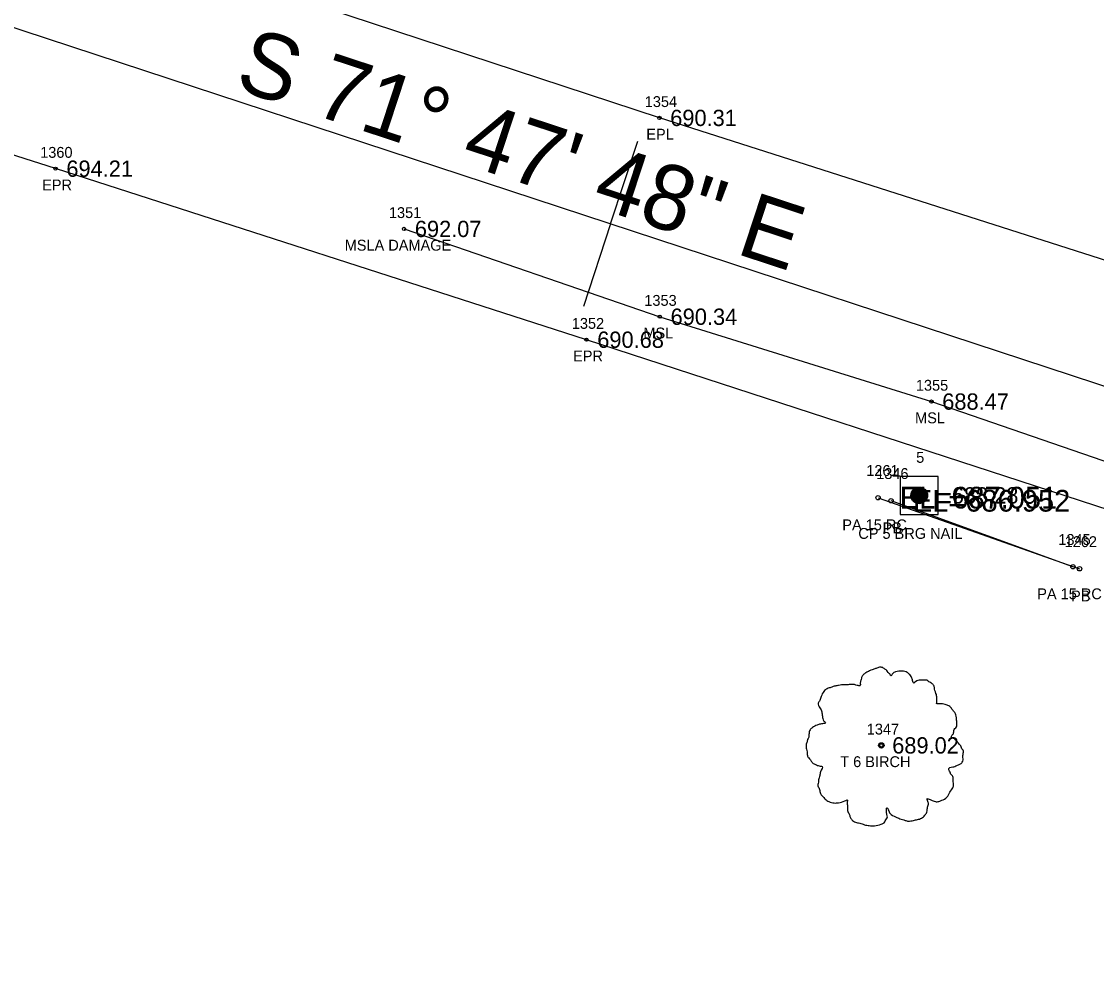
# Model space of a CAD drawing. Extents: x 1655137 to 1657928, y 1003994 to 1005407.
# Drawn here: x 1655840.3 to 1655939.3, y 1004715.5 to 1004802.9 of the extents above; entities that cross this region are included whole.
import ezdxf

# ---------------------------------------------------------------- set-up
doc = ezdxf.new("R2010")
doc.units = 0
for name, color, linetype in [('RD_EX_DR_Pipe', 7, 'Continuous'), ('RD_EX_DR_Pipe_txCode', 7, 'Continuous'), ('RD_EX_Misc', 7, 'Continuous'), ('RD_EX_Misc_txCode', 7, 'Continuous'), ('RD_EX_Road', 7, 'Continuous'), ('RD_EX_Road_txCode', 7, 'Continuous'), ('RD_EX_TX_Misc_ELEV', 7, 'Continuous'), ('RD_EX_TX_Road_ELEV', 7, 'Continuous'), ('RD_EX_TX_VEG_ELEV', 7, 'Continuous'), ('RD_EX_VEG', 7, 'Continuous'), ('RD_EX_VEG_txCode', 7, 'Continuous'), ('RD_HC_Cl', 7, 'Continuous'), ('RD_HC_Data', 7, 'Continuous'), ('RD_HC_Data_Tic', 7, 'Continuous'), ('RD_HC_Survey', 7, 'Continuous'), ('RD_HC_Survey_ELEV', 7, 'Continuous'), ('RD_HC_Survey_txCode', 7, 'Continuous'), ('RD_SMD_Locator', 7, 'Continuous'), ('RD_TX_Pipe_ElevEX', 7, 'Continuous')]:
    doc.layers.add(name, color=color, linetype=linetype)

msp = doc.modelspace()

# ---------------------------------------------------------------- linework, layer by layer
at = {"layer": 'RD_EX_DR_Pipe'}
for p, q in [((1655919.229, 1004759.066), (1655937.783, 1004752.518)), ((1655937.182, 1004752.714), (1655920.431, 1004758.784))]:
    msp.add_line(p, q, dxfattribs=at)
at = {"layer": 'RD_EX_Misc'}
msp.add_lwpolyline([(1655875.572, 1004783.81), (1655899.124, 1004775.727), (1655924.143, 1004767.915), (1655957.486, 1004756.441), (1655982.243, 1004748.48), (1656011.779, 1004739.501), (1656033.158, 1004732.174), (1656057.837, 1004724.625), (1656091.047, 1004714.315), (1656106.296, 1004710.837), (1656119.065, 1004707.85), (1656127.527, 1004711.026), (1656137.413, 1004709.544), (1656150.275, 1004705.031), (1656164.334, 1004699.598), (1656171.578, 1004694.85), (1656180.966, 1004693.871), (1656197.975, 1004688.492), (1656215.111, 1004682.576), (1656240.683, 1004675.392), (1656271.878, 1004665.005), (1656304.44, 1004655.084)], dxfattribs=at)
at = {"layer": 'RD_EX_Road'}
for points in [[(1656365.125, 1004639.993), (1656336.036, 1004649.337), (1656302.553, 1004660.365), (1656279.148, 1004668.232), (1656240.072, 1004681.052), (1656188.234, 1004698.028), (1656166.718, 1004705.508), (1656141.162, 1004714.063), (1656093.113, 1004730.113), (1656044.163, 1004746.75), (1655996.355, 1004762.445), (1655947.197, 1004778.676), (1655899.09, 1004794.03), (1655850.622, 1004809.986), (1655801.911, 1004826.095), (1655753.093, 1004842.312), (1655704.246, 1004858.105)], [(1656358.504, 1004619.827), (1656328.784, 1004629.475), (1656280.774, 1004645.393), (1656247.663, 1004656.111), (1656244.505, 1004656.516), (1656222.03, 1004663.569), (1656217.647, 1004665.963), (1656183.416, 1004677.324), (1656134.594, 1004693.716), (1656086.193, 1004709.749), (1656037.581, 1004726.126), (1655989.575, 1004741.988), (1655940.618, 1004757.879), (1655892.373, 1004773.61), (1655843.478, 1004789.356), (1655805.734, 1004801.404), (1655779.222, 1004810.434), (1655768.796, 1004813.103), (1655744.595, 1004822.13), (1655698.832, 1004837.654)]]:
    msp.add_lwpolyline(points, dxfattribs=at)
at = {"layer": 'RD_EX_VEG'}
for centre, radius in [((1655919.535, 1004736.26), 0.25), ((1655919.523, 1004736.241), 0.0001)]:
    msp.add_circle(centre, radius, dxfattribs=at)
for points in [[(1655919.667, 1004743.427), (1655919.367, 1004743.452), (1655919.042, 1004743.352), (1655918.792, 1004743.252), (1655918.568, 1004743.177), (1655918.343, 1004743.077), (1655918.043, 1004742.902), (1655917.818, 1004742.702), (1655917.693, 1004742.452), (1655917.643, 1004742.227), (1655917.593, 1004741.953), (1655917.593, 1004741.778), (1655917.468, 1004741.753), (1655917.318, 1004741.778), (1655917.068, 1004741.853), (1655916.818, 1004741.853), (1655916.568, 1004741.853), (1655916.219, 1004741.828), (1655915.869, 1004741.828), (1655915.594, 1004741.778), (1655915.269, 1004741.728), (1655914.894, 1004741.603), (1655914.544, 1004741.478), (1655914.244, 1004741.228), (1655913.995, 1004740.753), (1655913.87, 1004740.403), (1655913.72, 1004740.153), (1655913.87, 1004739.704), (1655914.045, 1004739.354), (1655914.069, 1004739.154), (1655914.144, 1004738.729), (1655914.244, 1004738.504), (1655914.369, 1004738.304), (1655914.294, 1004738.279), (1655913.92, 1004738.229), (1655913.62, 1004738.129), (1655913.195, 1004737.904), (1655912.97, 1004737.679), (1655912.87, 1004737.355), (1655912.845, 1004737.005), (1655912.745, 1004736.805), (1655912.67, 1004736.53), (1655912.645, 1004736.455), (1655912.595, 1004736.13), (1655912.695, 1004735.68), (1655912.72, 1004735.33), (1655912.845, 1004735.106), (1655912.995, 1004734.931), (1655913.17, 1004734.681), (1655913.57, 1004734.456), (1655913.895, 1004734.356), (1655914.094, 1004734.331), (1655913.92, 1004733.831), (1655913.87, 1004733.481), (1655913.745, 1004733.081), (1655913.745, 1004733.007), (1655913.695, 1004732.532), (1655913.845, 1004732.207), (1655913.92, 1004731.832), (1655914.094, 1004731.607), (1655914.369, 1004731.307), (1655914.694, 1004731.082), (1655915.194, 1004730.957), (1655915.594, 1004730.982), (1655916.169, 1004731.157), (1655916.418, 1004731.232), (1655916.393, 1004731.057), (1655916.418, 1004730.682), (1655916.418, 1004730.258), (1655916.568, 1004729.933), (1655916.668, 1004729.658), (1655916.818, 1004729.408), (1655917.143, 1004729.183), (1655917.543, 1004729.108), (1655917.968, 1004728.958), (1655918.418, 1004728.883), (1655918.917, 1004728.858), (1655919.517, 1004729.008), (1655919.792, 1004729.133), (1655919.892, 1004729.308), (1655920.092, 1004729.683), (1655920.042, 1004729.908), (1655920.067, 1004730.508), (1655920.167, 1004730.333), (1655920.342, 1004729.983), (1655920.842, 1004729.683), (1655921.241, 1004729.508), (1655921.716, 1004729.358), (1655922.016, 1004729.283), (1655922.491, 1004729.358), (1655922.866, 1004729.433), (1655923.24, 1004729.558), (1655923.54, 1004729.833), (1655923.715, 1004730.108), (1655923.765, 1004730.383), (1655923.84, 1004730.757), (1655923.89, 1004730.932)], [(1655923.89, 1004730.932), (1655923.815, 1004731.107), (1655923.765, 1004731.357), (1655923.84, 1004731.332), (1655924.015, 1004731.282), (1655924.29, 1004731.157), (1655924.515, 1004731.082), (1655924.84, 1004731.107), (1655925.115, 1004731.207), (1655925.564, 1004731.482), (1655925.839, 1004731.957), (1655926.114, 1004732.357), (1655926.189, 1004732.682), (1655926.139, 1004732.907), (1655926.114, 1004733.406), (1655925.914, 1004733.656), (1655925.864, 1004733.781), (1655925.764, 1004734.181), (1655925.839, 1004734.231), (1655926.114, 1004734.281), (1655926.489, 1004734.406), (1655926.764, 1004734.531), (1655926.989, 1004734.706), (1655927.064, 1004734.931), (1655927.039, 1004735.33), (1655927.089, 1004735.73), (1655927.014, 1004735.88), (1655926.914, 1004736.03), (1655926.839, 1004736.23), (1655926.689, 1004736.38), (1655926.589, 1004736.53), (1655926.489, 1004736.63), (1655926.364, 1004736.78), (1655926.189, 1004736.905), (1655926.039, 1004736.955), (1655925.989, 1004737.105), (1655926.139, 1004737.305), (1655926.189, 1004737.405), (1655926.214, 1004737.629), (1655926.439, 1004737.979), (1655926.489, 1004738.379), (1655926.439, 1004738.804), (1655926.389, 1004739.079), (1655926.239, 1004739.354), (1655926.039, 1004739.604), (1655925.914, 1004739.779), (1655925.739, 1004739.903), (1655925.415, 1004740.028), (1655925.165, 1004740.078), (1655924.815, 1004740.078), (1655924.615, 1004740.128), (1655924.64, 1004740.178), (1655924.64, 1004740.328), (1655924.64, 1004740.603), (1655924.565, 1004741.053), (1655924.415, 1004741.553), (1655924.415, 1004741.578), (1655924.315, 1004741.828), (1655924.09, 1004742.028), (1655923.915, 1004742.127), (1655923.715, 1004742.252), (1655923.465, 1004742.277), (1655923.166, 1004742.277), (1655922.891, 1004742.227), (1655922.691, 1004742.127), (1655922.516, 1004742.003), (1655922.441, 1004742.152), (1655922.341, 1004742.452), (1655922.291, 1004742.602), (1655922.141, 1004742.777), (1655921.916, 1004742.977), (1655921.466, 1004743.102), (1655920.842, 1004743.027), (1655920.542, 1004742.827), (1655920.392, 1004742.652), (1655920.342, 1004742.777), (1655920.142, 1004742.977), (1655920.042, 1004743.152), (1655919.867, 1004743.277), (1655919.717, 1004743.377), (1655919.617, 1004743.427)]]:
    msp.add_spline(points, degree=3, dxfattribs=at)
at = {"layer": 'RD_HC_Cl'}
msp.add_line((1655701.505, 1004847.777), (1656069.258, 1004726.842), dxfattribs=at)
at = {"layer": 'RD_HC_Data_Tic'}
for q in [(1655897.102, 1004791.876), (1655892.103, 1004776.677)]:
    msp.add_line((1655894.602, 1004784.277), q, dxfattribs=at)
at = {"layer": 'RD_HC_Survey'}
for p, q in [((1655922.301, 1004759.013), (1655922.301, 1004759.536)), ((1655922.325, 1004758.953), (1655922.325, 1004759.597)), ((1655922.35, 1004758.904), (1655922.35, 1004759.646)), ((1655922.375, 1004758.862), (1655922.375, 1004759.688)), ((1655922.399, 1004758.825), (1655922.399, 1004759.724)), ((1655922.424, 1004758.793), (1655922.424, 1004759.757)), ((1655922.449, 1004758.763), (1655922.449, 1004759.786)), ((1655922.474, 1004758.737), (1655922.474, 1004759.812)), ((1655922.498, 1004758.713), (1655922.498, 1004759.837)), ((1655922.523, 1004758.691), (1655922.523, 1004759.859)), ((1655922.548, 1004758.67), (1655922.548, 1004759.879)), ((1655922.573, 1004758.652), (1655922.573, 1004759.898)), ((1655922.597, 1004758.634), (1655922.597, 1004759.915)), ((1655922.622, 1004758.618), (1655922.622, 1004759.931)), ((1655922.647, 1004758.604), (1655922.647, 1004759.945)), ((1655922.672, 1004758.591), (1655922.672, 1004759.959)), ((1655922.696, 1004758.578), (1655922.696, 1004759.971)), ((1655922.721, 1004758.567), (1655922.721, 1004759.982)), ((1655922.746, 1004758.557), (1655922.746, 1004759.992)), ((1655922.771, 1004758.548), (1655922.771, 1004760.001)), ((1655922.795, 1004758.54), (1655922.795, 1004760.009)), ((1655922.82, 1004758.533), (1655922.82, 1004760.017)), ((1655922.845, 1004758.526), (1655922.845, 1004760.023)), ((1655922.87, 1004758.521), (1655922.87, 1004760.029)), ((1655922.894, 1004758.516), (1655922.894, 1004760.033)), ((1655922.919, 1004758.512), (1655922.919, 1004760.037)), ((1655922.944, 1004758.509), (1655922.944, 1004760.04)), ((1655922.969, 1004758.507), (1655922.969, 1004760.042)), ((1655922.993, 1004758.506), (1655922.993, 1004760.044)), ((1655923.018, 1004758.505), (1655923.018, 1004760.044)), ((1655923.043, 1004758.505), (1655923.043, 1004760.044)), ((1655923.068, 1004758.506), (1655923.068, 1004760.043)), ((1655923.092, 1004758.508), (1655923.092, 1004760.041)), ((1655923.117, 1004758.511), (1655923.117, 1004760.039)), ((1655923.142, 1004758.514), (1655923.142, 1004760.035)), ((1655923.167, 1004758.519), (1655923.167, 1004760.031)), ((1655923.191, 1004758.524), (1655923.191, 1004760.026)), ((1655923.216, 1004758.53), (1655923.216, 1004760.02)), ((1655923.241, 1004758.536), (1655923.241, 1004760.013)), ((1655923.266, 1004758.544), (1655923.266, 1004760.005)), ((1655923.29, 1004758.553), (1655923.29, 1004759.997)), ((1655923.315, 1004758.562), (1655923.315, 1004759.987)), ((1655923.34, 1004758.573), (1655923.34, 1004759.976)), ((1655923.365, 1004758.585), (1655923.365, 1004759.965)), ((1655923.389, 1004758.597), (1655923.389, 1004759.952)), ((1655923.414, 1004758.611), (1655923.414, 1004759.938)), ((1655923.439, 1004758.627), (1655923.439, 1004759.923)), ((1655923.464, 1004758.643), (1655923.464, 1004759.906)), ((1655923.488, 1004758.661), (1655923.488, 1004759.888)), ((1655923.513, 1004758.681), (1655923.513, 1004759.869)), ((1655923.538, 1004758.702), (1655923.538, 1004759.847)), ((1655923.563, 1004758.725), (1655923.563, 1004759.824)), ((1655923.587, 1004758.751), (1655923.587, 1004759.799)), ((1655923.612, 1004758.778), (1655923.612, 1004759.771)), ((1655923.637, 1004758.809), (1655923.637, 1004759.74)), ((1655923.662, 1004758.844), (1655923.662, 1004759.706)), ((1655923.686, 1004758.883), (1655923.686, 1004759.666)), ((1655923.711, 1004758.928), (1655923.711, 1004759.621)), ((1655923.736, 1004758.982), (1655923.736, 1004759.567)), ((1655922.276, 1004759.096), (1655922.276, 1004759.454)), ((1655923.761, 1004759.052), (1655923.761, 1004759.497)), ((1655923.785, 1004759.163), (1655923.785, 1004759.386))]:
    msp.add_line(p, q, dxfattribs=at)
msp.add_lwpolyline([(1655924.774, 1004761.025), (1655921.274, 1004761.025), (1655921.274, 1004757.525), (1655924.774, 1004757.525)], close=True, dxfattribs=at)
msp.add_circle((1655923.024, 1004759.275), 0.769, dxfattribs=at)
at = {"layer": 'RD_SMD_Locator'}
for centre, radius in [((1655899.09, 1004794.03), 0.15), ((1655843.478, 1004789.356), 0.15), ((1655875.572, 1004783.81), 0.15), ((1655899.124, 1004775.727), 0.15), ((1655892.373, 1004773.61), 0.15), ((1655924.143, 1004767.915), 0.15), ((1655919.229, 1004759.066), 0.2), ((1655920.431, 1004758.784), 0.2), ((1655923.024, 1004759.275), 0.15), ((1655937.182, 1004752.714), 0.2), ((1655937.783, 1004752.518), 0.2), ((1655919.535, 1004736.26), 0.15)]:
    msp.add_circle(centre, radius, dxfattribs=at)

# ---------------------------------------------------------------- texts
at = {"layer": 'RD_EX_DR_Pipe_txCode'}
for s, p in [('1261', (1655918.142, 1004761.066)), ('1346', (1655919.061, 1004760.784)), ('PA 15 RC', (1655915.937, 1004756.066)), ('PB', (1655919.651, 1004755.784)), ('1345', (1655935.836, 1004754.714)), ('1262', (1655936.413, 1004754.518)), ('PA 15 RC', (1655933.891, 1004749.714)), ('PB', (1655937.003, 1004749.518))]:
    msp.add_text(s, height=1, dxfattribs=at).set_placement(p)
at = {"layer": 'RD_EX_Misc_txCode'}
for s, p in [('1351', (1655874.185, 1004784.81)), ('MSLA DAMAGE', (1655870.113, 1004781.81)), ('1353', (1655897.707, 1004776.727)), ('MSL', (1655897.621, 1004773.727)), ('1355', (1655922.714, 1004768.915)), ('MSL', (1655922.64, 1004765.915))]:
    msp.add_text(s, height=1, dxfattribs=at).set_placement(p)
at = {"layer": 'RD_EX_Road_txCode'}
for s, p in [('1354', (1655897.744, 1004795.03)), ('EPL', (1655897.886, 1004792.03)), ('1360', (1655842.068, 1004790.356)), ('EPR', (1655842.25, 1004787.356)), ('1352', (1655891.027, 1004774.61)), ('EPR', (1655891.145, 1004771.61))]:
    msp.add_text(s, height=1, dxfattribs=at).set_placement(p)
at = {"layer": 'RD_EX_TX_Misc_ELEV'}
for s, p in [('692.07', (1655876.572, 1004783.06)), ('690.34', (1655900.124, 1004774.977)), ('688.47', (1655925.143, 1004767.165))]:
    msp.add_text(s, height=1.5, dxfattribs=at).set_placement(p)
at = {"layer": 'RD_EX_TX_Road_ELEV'}
for s, p in [('690.31', (1655900.09, 1004793.28)), ('694.21', (1655844.478, 1004788.606)), ('690.68', (1655893.373, 1004772.86))]:
    msp.add_text(s, height=1.5, dxfattribs=at).set_placement(p)
at = {"layer": 'RD_EX_TX_VEG_ELEV'}
msp.add_text('689.02', height=1.5, dxfattribs=at).set_placement((1655920.535, 1004735.51))
at = {"layer": 'RD_EX_VEG_txCode'}
for s, p in [('1347', (1655918.189, 1004737.26)), ('T 6 BIRCH', (1655915.748, 1004734.26))]:
    msp.add_text(s, height=1, dxfattribs=at).set_placement(p)
at = {"layer": 'RD_HC_Data'}
msp.add_text('S 71%%d 47\' 48" E', height=6, rotation=341.79663, dxfattribs=at).set_placement((1655859.815, 1004796.769))
at = {"layer": 'RD_HC_Survey_ELEV'}
msp.add_text('688.28', height=1.5, dxfattribs=at).set_placement((1655926.024, 1004758.525))
at = {"layer": 'RD_HC_Survey_txCode'}
for s, p in [('5', (1655922.741, 1004762.275)), ('CP 5 BRG NAIL', (1655917.41, 1004755.275))]:
    msp.add_text(s, height=1, dxfattribs=at).set_placement(p)
at = {"layer": 'RD_TX_Pipe_ElevEX'}
for s, p in [('EL=687.051', (1655921.229, 1004758.066)), ('EL=686.952', (1655922.431, 1004757.784))]:
    msp.add_text(s, height=2, dxfattribs=at).set_placement(p)

doc.saveas('drawing.dxf')
